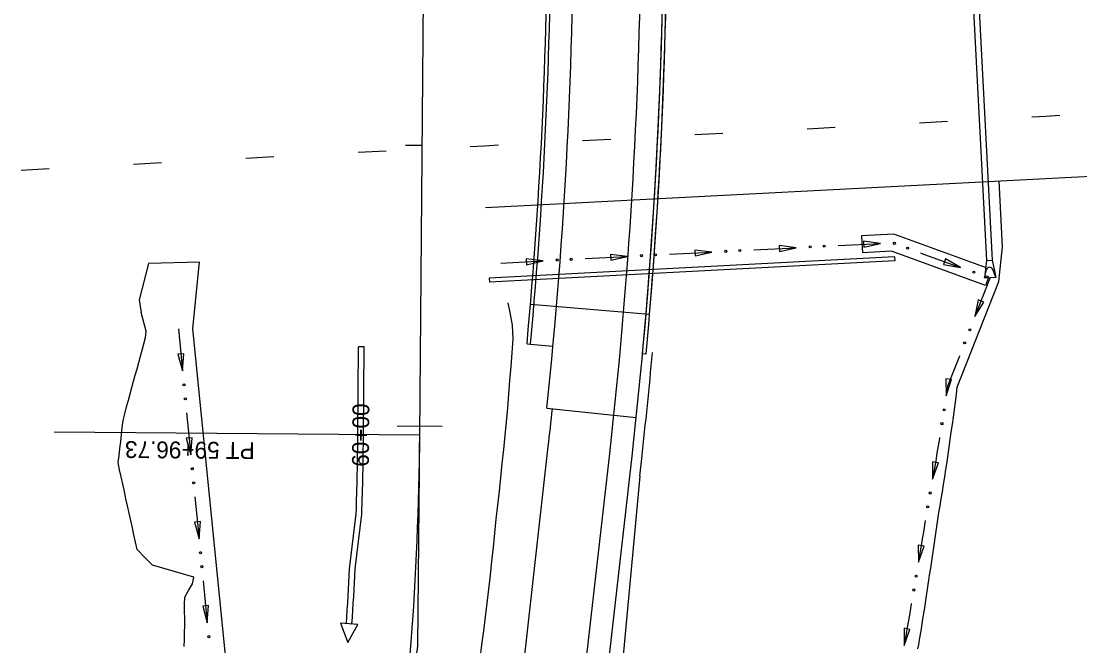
# Model space of a CAD drawing. Extents: x 1304554 to 1314558, y 2088110 to 2090513.
# Drawn here: x 1313855.1 to 1314231.7, y 2089040.4 to 2089262.8 of the extents above; entities that cross this region are included whole.
import ezdxf

# ---------------------------------------------------------------- set-up
doc = ezdxf.new("R2010")
doc.units = 0
for name, color, linetype in [('B-Sub-Retaining Wall', 7, 'Continuous'), ('MOT_Barrier Wall Stage 3', 7, 'Continuous'), ('MOT_TIAB_Stage 3', 7, 'Continuous'), ('R_Bridge', 7, 'Continuous'), ('R_Conc Ditch Paving', 7, 'Continuous'), ('R_Drainage', 7, 'Continuous'), ('R_Horz Alg', 7, 'Continuous'), ('R_Horz Alg Annot', 7, 'Continuous'), ('R_Horz Alg Stationing', 7, 'Continuous'), ('R_Proposed Const Limits', 7, 'Continuous'), ('R_Proposed Road', 7, 'Continuous'), ('R_Shld_GR', 7, 'Continuous'), ('R_Shoulder', 7, 'Continuous'), ('R_Special Ditch', 7, 'Continuous'), ('S_Striping', 7, 'Continuous')]:
    doc.layers.add(name, color=color, linetype=linetype)

msp = doc.modelspace()

# ---------------------------------------------------------------- linework, layer by layer
at = {"layer": 'B-Sub-Retaining Wall'}
for p, q in [((1314165.86, 2089178.92), (1314021.63, 2089171.31)), ((1314165.86, 2089178.92), (1314165.94, 2089177.42)), ((1314165.86, 2089178.92), (1314165.94, 2089177.42)), ((1314165.86, 2089178.92), (1314165.94, 2089177.42)), ((1314165.94, 2089177.42), (1314021.71, 2089169.82)), ((1314021.63, 2089171.31), (1314021.71, 2089169.82))]:
    msp.add_line(p, q, dxfattribs=at)
at = {"layer": 'MOT_Barrier Wall Stage 3'}
for p, q in [((1313974.91, 2089115.57), (1313975.18, 2089146.84)), ((1313977.18, 2089146.82), (1313975.18, 2089146.84)), ((1313976.91, 2089115.55), (1313977.18, 2089146.82)), ((1313971.97, 2089067.87), (1313974.31, 2089087.39)), ((1313973.97, 2089067.77), (1313976.31, 2089087.33)), ((1313972.8, 2089048.18), (1313970.8, 2089048.32))]:
    msp.add_line(p, q, dxfattribs=at)
for radius, start, end in [(1123.92, 358.06349, 359.5), (1125.92, 358.06349, 359.5), (1122.42, 356.06349, 357.06349), (1124.42, 356.06349, 357.06349)]:
    msp.add_arc((1312851.03, 2089125.37), radius, start, end, dxfattribs=at)
at = {"layer": 'MOT_TIAB_Stage 3'}
msp.add_lwpolyline([(1313971.34, 2089041.59), (1313974.93, 2089048.04), (1313968.67, 2089048.47)], close=True, dxfattribs=at)
at = {"layer": 'R_Bridge'}
for p, q in [((1314078.66, 2089158.36), (1314036.31, 2089161.9)), ((1314035.08, 2089147.95), (1314036.32, 2089147.85)), ((1314076.19, 2089144.52), (1314077.43, 2089144.42))]:
    msp.add_line(p, q, dxfattribs=at)
for radius, start, end in [(1782.95, 354.7437, 5.46314), (1784.2, 354.74404, 5.4628), (1741.7, 354.73222, 5.47462), (1742.95, 354.73258, 5.47426), (1782.95, 355.19361, 5.01323), (1784.2, 355.19363, 5.01321)]:
    msp.add_arc((1312300.74, 2089307.86), radius, start, end, dxfattribs=at)
at = {"layer": 'R_Conc Ditch Paving'}
for p, q in [((1314154.11, 2089186.35), (1314154.43, 2089180.35)), ((1314199.19, 2089171.54), (1314198.16, 2089168.72))]:
    msp.add_line(p, q, dxfattribs=at)
for points in [[(1314198.22, 2089175.08), (1314165.59, 2089186.94), (1314154.11, 2089186.35)], [(1314198.16, 2089168.72), (1314164.68, 2089180.89), (1314154.43, 2089180.35)]]:
    msp.add_lwpolyline(points, dxfattribs=at)
at = {"layer": 'R_Drainage'}
for p, q in [((1314193.48, 2089274.5), (1314198.5, 2089177.63)), ((1314195.48, 2089274.6), (1314200.5, 2089177.73)), ((1314198.5, 2089177.63), (1314197.82, 2089171.47)), ((1314198.5, 2089177.63), (1314200.5, 2089177.73)), ((1314200.5, 2089177.73), (1314201.82, 2089171.67)), ((1314197.82, 2089171.47), (1314198.57, 2089174.31)), ((1314197.82, 2089171.47), (1314201.82, 2089171.67)), ((1314201.82, 2089171.67), (1314200.78, 2089174.42)), ((1313912.99, 2089144.4), (1313910.88, 2089144.2)), ((1313912.52, 2089138.33), (1313912.99, 2089144.4)), ((1313910.88, 2089144.2), (1313912.52, 2089138.33)), ((1313915.93, 2089114.51), (1313913.82, 2089114.3)), ((1313913.82, 2089114.3), (1313915.46, 2089108.43)), ((1313915.46, 2089108.43), (1313915.93, 2089114.51)), ((1313918.87, 2089084.62), (1313916.76, 2089084.41)), ((1313916.76, 2089084.41), (1313918.4, 2089078.54)), ((1313918.4, 2089078.54), (1313918.87, 2089084.62)), ((1313921.81, 2089054.72), (1313919.7, 2089054.51)), ((1313919.7, 2089054.51), (1313921.34, 2089048.65)), ((1313921.34, 2089048.65), (1313921.81, 2089054.72))]:
    msp.add_line(p, q, dxfattribs=at)
for points in [[(1313911.06, 2089153.26), (1313912.52, 2089138.33)], [(1313913.99, 2089123.4), (1313913.99, 2089123.36)], [(1313913.99, 2089123.36), (1313915.46, 2089108.43)], [(1313916.93, 2089093.51), (1313916.93, 2089093.47)], [(1313916.93, 2089093.47), (1313918.4, 2089078.54)], [(1313919.87, 2089063.61), (1313919.88, 2089063.58)], [(1313919.88, 2089063.57), (1313921.34, 2089048.65)]]:
    msp.add_lwpolyline(points, dxfattribs=at)
for centre in [(1313913.05, 2089133.35), (1313913.54, 2089128.36), (1313915.99, 2089103.46), (1313916.48, 2089098.47), (1313918.93, 2089073.56), (1313919.42, 2089068.58), (1313921.87, 2089043.67)]:
    msp.add_circle(centre, 0.375, dxfattribs=at)
msp.add_arc((1314199.69, 2089174.02), 1.17, 20.4966, 165.4367, dxfattribs=at)
at = {"layer": 'R_Horz Alg'}
msp.add_line((1313996.9, 2089115.37), (1314000.02, 2089472.84), dxfattribs=at)
msp.add_line((1313996.9, 2089115.37), (1314000.02, 2089472.84), dxfattribs=at)
msp.add_arc((1312851.03, 2089125.37), 1145.92, 352, 359.5, dxfattribs=at)
msp.add_arc((1312851.03, 2089125.37), 1145.92, 352, 359.5, dxfattribs=at)
at = {"layer": 'R_Horz Alg Annot'}
for points in [[(1313996.9, 2089115.37), (1313866.91, 2089116.51)], [(1313985.8, 2088965.89), (1313996.25, 2089040.27), (1313996.9, 2089115.37)]]:
    msp.add_lwpolyline(points, dxfattribs=at)
at = {"layer": 'R_Horz Alg Stationing'}
for points in [[(1313991.81, 2089218.69), (1313997.81, 2089218.64)], [(1313988.93, 2089118.71), (1314004.93, 2089118.57)]]:
    msp.add_lwpolyline(points, dxfattribs=at)
at = {"layer": 'R_Proposed Const Limits'}
for points in [[(1314174.12, 2089039.32), (1314174.42, 2089040.86), (1314174.87, 2089043.32), (1314175.26, 2089045.79), (1314175.65, 2089048.27), (1314176.04, 2089050.74), (1314176.42, 2089053.21), (1314176.8, 2089055.68), (1314177.18, 2089058.16), (1314177.56, 2089060.63), (1314177.94, 2089063.1), (1314178.03, 2089063.69), (1314178.31, 2089065.58), (1314178.69, 2089068.05), (1314179.06, 2089070.52), (1314179.43, 2089073), (1314179.8, 2089075.47), (1314180.16, 2089077.95), (1314180.53, 2089080.42), (1314180.89, 2089082.9), (1314181.26, 2089085.37), (1314181.63, 2089087.84), (1314182.04, 2089090.31), (1314182.46, 2089092.78), (1314182.89, 2089095.25), (1314183.29, 2089097.89), (1314183.7, 2089100.55), (1314184.09, 2089103.21), (1314184.49, 2089105.87), (1314184.87, 2089108.53), (1314185.26, 2089111.19), (1314185.64, 2089113.85), (1314186.01, 2089116.51), (1314186.38, 2089119.18), (1314186.74, 2089121.84), (1314187.1, 2089124.51), (1314187.46, 2089127.17), (1314187.81, 2089129.84), (1314188.15, 2089132.51), (1314202.91, 2089170.09), (1314204.27, 2089182.4), (1314203.05, 2089205.9)], [(1313916.24, 2089153.35), (1313918.62, 2089176.96), (1313900.37, 2089176.49), (1313897.09, 2089163.58), (1313897.83, 2089159.07)], [(1314018.38, 2089035.82), (1314019.01, 2089040.78), (1314019.66, 2089045.74), (1314020.32, 2089050.7), (1314020.95, 2089055.66), (1314021.49, 2089060.63), (1314022.03, 2089065.6), (1314022.57, 2089070.57), (1314023.12, 2089075.54), (1314023.62, 2089080.51), (1314024.15, 2089085.49), (1314024.69, 2089090.46), (1314025.23, 2089095.43), (1314025.73, 2089100.4), (1314026.25, 2089105.38), (1314026.79, 2089110.35), (1314027.33, 2089115.28), (1314027.81, 2089120.19), (1314028.21, 2089125.1), (1314028.59, 2089130.01), (1314028.98, 2089134.93), (1314029.38, 2089139.84), (1314029.75, 2089144.75), (1314030.11, 2089149.66), (1314029.94, 2089154.62), (1314029.01, 2089159.64), (1314028.32, 2089162.56)], [(1313913.14, 2089040.15), (1313913.18, 2089042.66), (1313913.23, 2089045.17), (1313913.32, 2089047.67), (1313913.35, 2089050.19), (1313913.29, 2089052.71), (1313913.23, 2089055.23), (1313913.32, 2089057.74), (1313914.62, 2089060.11), (1313916.07, 2089062.46), (1313916.56, 2089064.92), (1313901.85, 2089069.09), (1313900.83, 2089070.16), (1313899.15, 2089071.92), (1313896.44, 2089074.74), (1313895.82, 2089077.32), (1313895.25, 2089079.9), (1313894.68, 2089082.48), (1313894.12, 2089085.06), (1313893.55, 2089087.64), (1313892.99, 2089090.22), (1313892.42, 2089092.8), (1313891.85, 2089095.38), (1313891.72, 2089095.99), (1313891.29, 2089097.96), (1313890.72, 2089100.54), (1313890.16, 2089103.12), (1313889.67, 2089105.69), (1313889.96, 2089108.17), (1313890.25, 2089110.66), (1313890.53, 2089113.14), (1313890.82, 2089115.62), (1313891.11, 2089118.11), (1313891.4, 2089120.59), (1313891.96, 2089123.04), (1313892.63, 2089125.48), (1313893.29, 2089127.93), (1313893.91, 2089130.17), (1313894.51, 2089132.39), (1313895.12, 2089134.61), (1313895.73, 2089136.83), (1313896.34, 2089139.05), (1313896.94, 2089141.28), (1313897.55, 2089143.5), (1313898.16, 2089145.73), (1313898.77, 2089147.96), (1313899.38, 2089150.18), (1313899.63, 2089152.45), (1313897.83, 2089159.07)], [(1313914.54, 2088809.73), (1313912.39, 2088821.75), (1313931.7, 2088908.87), (1313933.34, 2088937.28), (1313931.57, 2088998.96), (1313916.24, 2089153.35)]]:
    msp.add_lwpolyline(points, dxfattribs=at)
at = {"layer": 'R_Proposed Road'}
for p, q in [((1314036.32, 2089147.85), (1314044.29, 2089147.11)), ((1314042.12, 2089125.05), (1314073.94, 2089121.71)), ((1313991.22, 2088655.7), (1314042.63, 2089111.32)), ((1314013.09, 2088653.23), (1314064.49, 2089108.85))]:
    msp.add_line(p, q, dxfattribs=at)
for radius, start, end in [(1750.95, 354.00707, 6.20458), (1774.95, 353.5625, 5.5), (1774.95, 353.5625, 5.5), (1752.95, 353.5625, 354.00707)]:
    msp.add_arc((1312300.74, 2089307.86), radius, start, end, dxfattribs=at)
at = {"layer": 'R_Shld_GR'}
for p, q in [((1314075.16, 2089100.8), (1314075.87, 2089107.15)), ((1314075.17, 2089100.87), (1314059.02, 2088926.55))]:
    msp.add_line(p, q, dxfattribs=at)
msp.add_arc((1312300.69, 2089307.45), 1786.45, 353.5625, 354.77698, dxfattribs=at)
at = {"layer": 'R_Shoulder'}
for p, q in [((1314020.3, 2089196.43), (1314557.57, 2089224.28)), ((1314021.03, 2088652.34), (1314072.44, 2089107.95))]:
    msp.add_line(p, q, dxfattribs=at)
msp.add_arc((1312300.74, 2089307.86), 1782.95, 353.5625, 5.5, dxfattribs=at)
at = {"layer": 'R_Special Ditch'}
for p, q in [((1314130.8, 2089182.13), (1314124.75, 2089182.88)), ((1314124.75, 2089182.88), (1314124.86, 2089180.77)), ((1314130.8, 2089182.13), (1314124.75, 2089182.88)), ((1314124.75, 2089182.88), (1314124.86, 2089180.77)), ((1314124.86, 2089180.77), (1314130.8, 2089182.13)), ((1314124.86, 2089180.77), (1314130.8, 2089182.13)), ((1314160.79, 2089183.69), (1314154.75, 2089184.43)), ((1314154.75, 2089184.43), (1314154.86, 2089182.32)), ((1314160.79, 2089183.69), (1314154.75, 2089184.43)), ((1314154.75, 2089184.43), (1314154.86, 2089182.32)), ((1314154.86, 2089182.32), (1314160.79, 2089183.69)), ((1314154.86, 2089182.32), (1314160.79, 2089183.69)), ((1314070.8, 2089179.02), (1314064.75, 2089179.77)), ((1314064.75, 2089179.77), (1314064.86, 2089177.66)), ((1314070.8, 2089179.02), (1314064.75, 2089179.77)), ((1314064.75, 2089179.77), (1314064.86, 2089177.66)), ((1314064.86, 2089177.66), (1314070.8, 2089179.02)), ((1314064.86, 2089177.66), (1314070.8, 2089179.02)), ((1314100.8, 2089180.58), (1314094.75, 2089181.32)), ((1314094.75, 2089181.32), (1314094.86, 2089179.21)), ((1314100.8, 2089180.58), (1314094.75, 2089181.32)), ((1314094.75, 2089181.32), (1314094.86, 2089179.21)), ((1314094.86, 2089179.21), (1314100.8, 2089180.58)), ((1314094.86, 2089179.21), (1314100.8, 2089180.58)), ((1314040.8, 2089177.47), (1314034.76, 2089178.22)), ((1314034.76, 2089178.22), (1314034.86, 2089176.1)), ((1314040.8, 2089177.47), (1314034.76, 2089178.22)), ((1314034.76, 2089178.22), (1314034.86, 2089176.1)), ((1314034.86, 2089176.1), (1314040.8, 2089177.47)), ((1314034.86, 2089176.1), (1314040.8, 2089177.47)), ((1314184, 2089178.18), (1314183.28, 2089176.19)), ((1314184, 2089178.18), (1314183.28, 2089176.19)), ((1314183.28, 2089176.19), (1314189.28, 2089175.14)), ((1314183.28, 2089176.19), (1314189.28, 2089175.14)), ((1314189.28, 2089175.14), (1314184, 2089178.18)), ((1314189.28, 2089175.14), (1314184, 2089178.18)), ((1314195.56, 2089163.57), (1314194.37, 2089157.6)), ((1314195.56, 2089163.57), (1314194.37, 2089157.6)), ((1314197.53, 2089162.8), (1314195.56, 2089163.57)), ((1314197.53, 2089162.8), (1314195.56, 2089163.57)), ((1314194.37, 2089157.6), (1314197.53, 2089162.8)), ((1314194.37, 2089157.6), (1314197.53, 2089162.8)), ((1314186.12, 2089135.19), (1314184.03, 2089135.51)), ((1314184.03, 2089135.51), (1314184.19, 2089129.42)), ((1314186.12, 2089135.19), (1314184.03, 2089135.51)), ((1314184.03, 2089135.51), (1314184.19, 2089129.42)), ((1314184.19, 2089129.42), (1314186.12, 2089135.19)), ((1314184.19, 2089129.42), (1314186.12, 2089135.19)), ((1314181.41, 2089105.51), (1314179.32, 2089105.87)), ((1314179.32, 2089105.87), (1314179.34, 2089099.77)), ((1314181.41, 2089105.51), (1314179.32, 2089105.87)), ((1314179.32, 2089105.87), (1314179.34, 2089099.77)), ((1314179.34, 2089099.77), (1314181.41, 2089105.51)), ((1314179.34, 2089099.77), (1314181.41, 2089105.51)), ((1314176.33, 2089075.91), (1314174.24, 2089076.26)), ((1314174.24, 2089076.26), (1314174.3, 2089070.16)), ((1314176.33, 2089075.91), (1314174.24, 2089076.26)), ((1314174.24, 2089076.26), (1314174.3, 2089070.16)), ((1314174.3, 2089070.16), (1314176.33, 2089075.91)), ((1314174.3, 2089070.16), (1314176.33, 2089075.91)), ((1314171.31, 2089046.28), (1314169.22, 2089046.65)), ((1314169.22, 2089046.65), (1314169.23, 2089040.56)), ((1314171.31, 2089046.28), (1314169.22, 2089046.65)), ((1314169.22, 2089046.65), (1314169.23, 2089040.56)), ((1314169.23, 2089040.56), (1314171.31, 2089046.28)), ((1314169.23, 2089040.56), (1314171.31, 2089046.28))]:
    msp.add_line(p, q, dxfattribs=at)
for points in [[(1314115.82, 2089181.36), (1314130.8, 2089182.13)], [(1314115.82, 2089181.36), (1314130.8, 2089182.13)], [(1314145.78, 2089182.91), (1314145.81, 2089182.91)], [(1314145.78, 2089182.91), (1314145.81, 2089182.91)], [(1314145.81, 2089182.91), (1314160.79, 2089183.69)], [(1314145.81, 2089182.91), (1314160.79, 2089183.69)], [(1314055.82, 2089178.25), (1314070.8, 2089179.02)], [(1314055.82, 2089178.25), (1314070.8, 2089179.02)], [(1314085.78, 2089179.8), (1314085.82, 2089179.8)], [(1314085.78, 2089179.8), (1314085.82, 2089179.8)], [(1314085.82, 2089179.8), (1314100.8, 2089180.58)], [(1314085.82, 2089179.8), (1314100.8, 2089180.58)], [(1314115.78, 2089181.35), (1314115.81, 2089181.36)], [(1314115.78, 2089181.35), (1314115.81, 2089181.36)], [(1314175.15, 2089180.27), (1314175.18, 2089180.26)], [(1314175.15, 2089180.27), (1314175.18, 2089180.26)], [(1314175.18, 2089180.26), (1314189.28, 2089175.14)], [(1314175.18, 2089180.26), (1314189.28, 2089175.14)], [(1314025.82, 2089176.69), (1314040.8, 2089177.47)], [(1314025.82, 2089176.69), (1314040.8, 2089177.47)], [(1314055.78, 2089178.25), (1314055.82, 2089178.25)], [(1314055.78, 2089178.25), (1314055.82, 2089178.25)], [(1314199.82, 2089171.57), (1314194.37, 2089157.6)], [(1314199.82, 2089171.57), (1314194.37, 2089157.6)], [(1314188.9, 2089143.59), (1314184.7, 2089132.83), (1314184.3, 2089130.17), (1314184.19, 2089129.42)], [(1314188.9, 2089143.59), (1314184.7, 2089132.83), (1314184.3, 2089130.17), (1314184.19, 2089129.42)], [(1314188.91, 2089143.62), (1314188.9, 2089143.59)], [(1314188.91, 2089143.62), (1314188.9, 2089143.59)], [(1314181.84, 2089114.56), (1314181.79, 2089114.25), (1314181.35, 2089111.6), (1314180.91, 2089108.95), (1314180.46, 2089106.3), (1314180.01, 2089103.65), (1314179.55, 2089101), (1314179.34, 2089099.77)], [(1314181.84, 2089114.56), (1314181.79, 2089114.25), (1314181.35, 2089111.6), (1314180.91, 2089108.95), (1314180.46, 2089106.3), (1314180.01, 2089103.65), (1314179.55, 2089101), (1314179.34, 2089099.77)], [(1314181.85, 2089114.6), (1314181.84, 2089114.56)], [(1314181.85, 2089114.6), (1314181.84, 2089114.56)], [(1314176.74, 2089084.96), (1314176.48, 2089083.39), (1314176.08, 2089080.92), (1314175.67, 2089078.45), (1314175.27, 2089075.98), (1314174.86, 2089073.51), (1314174.45, 2089071.04), (1314174.3, 2089070.16)], [(1314176.74, 2089084.96), (1314176.48, 2089083.39), (1314176.08, 2089080.92), (1314175.67, 2089078.45), (1314175.27, 2089075.98), (1314174.86, 2089073.51), (1314174.45, 2089071.04), (1314174.3, 2089070.16)], [(1314176.74, 2089085), (1314176.74, 2089084.96)], [(1314176.74, 2089085), (1314176.74, 2089084.96)], [(1314171.79, 2089055.34), (1314171.52, 2089053.76), (1314171.1, 2089051.29), (1314170.67, 2089048.83), (1314170.24, 2089046.36), (1314169.81, 2089043.89), (1314169.38, 2089041.43), (1314169.23, 2089040.56)], [(1314171.79, 2089055.34), (1314171.52, 2089053.76), (1314171.1, 2089051.29), (1314170.67, 2089048.83), (1314170.24, 2089046.36), (1314169.81, 2089043.89), (1314169.38, 2089041.43), (1314169.23, 2089040.56)], [(1314171.8, 2089055.37), (1314171.79, 2089055.34)], [(1314171.8, 2089055.37), (1314171.79, 2089055.34)]]:
    msp.add_lwpolyline(points, dxfattribs=at)
for centre in [(1314135.79, 2089182.43), (1314135.79, 2089182.43), (1314140.8, 2089182.69), (1314140.8, 2089182.69), (1314165.77, 2089183.72), (1314165.77, 2089183.72), (1314170.47, 2089182.01), (1314170.47, 2089182.01), (1314050.8, 2089178.02), (1314050.8, 2089178.02), (1314075.8, 2089179.32), (1314075.8, 2089179.32), (1314080.8, 2089179.58), (1314080.8, 2089179.58), (1314105.79, 2089180.87), (1314105.79, 2089180.87), (1314110.8, 2089181.13), (1314110.8, 2089181.13), (1314045.8, 2089177.76), (1314045.8, 2089177.76), (1314194, 2089173.46), (1314194, 2089173.46), (1314198.71, 2089171.75), (1314198.71, 2089171.75), (1314192.58, 2089152.92), (1314192.58, 2089152.92), (1314190.76, 2089148.25), (1314190.76, 2089148.25), (1314183.46, 2089124.46), (1314183.46, 2089124.46), (1314182.68, 2089119.52), (1314182.68, 2089119.52), (1314178.49, 2089094.84), (1314178.49, 2089094.84), (1314177.6, 2089089.91), (1314177.6, 2089089.91), (1314173.51, 2089065.22), (1314173.51, 2089065.22), (1314172.67, 2089060.28), (1314172.67, 2089060.28)]:
    msp.add_circle(centre, 0.375, dxfattribs=at)
at = {"layer": 'S_Striping'}
for p, q in [((1314174.68, 2089226.63), (1314184.67, 2089227.16)), ((1314054.85, 2089220.29), (1314064.84, 2089220.82)), ((1314094.8, 2089222.42), (1314104.78, 2089222.94)), ((1313974.96, 2089216.13), (1313984.95, 2089216.65)), ((1313895.07, 2089211.89), (1313905.06, 2089212.42)), ((1313855.13, 2089209.77), (1313865.11, 2089210.3))]:
    msp.add_line(p, q, dxfattribs=at)
for points in [[(1314214.63, 2089228.75), (1314219.62, 2089229.01), (1314224.61, 2089229.28)], [(1314134.74, 2089224.52), (1314144.72, 2089225.05), (1314144.73, 2089225.05)], [(1314014.91, 2089218.21), (1314019.9, 2089218.47), (1314024.89, 2089218.73)], [(1313935.02, 2089214.02), (1313945, 2089214.56), (1313945, 2089214.56)]]:
    msp.add_lwpolyline(points, dxfattribs=at)

# ---------------------------------------------------------------- texts
at = {"layer": 'R_Horz Alg Annot'}
msp.add_text('PT 59+96.73', height=6, rotation=179.5, dxfattribs=at).set_placement((1313938.25, 2089112.89))
at = {"layer": 'R_Horz Alg Stationing'}
msp.add_text('60+00', height=6, rotation=89.5, dxfattribs=at).set_placement((1313978.81, 2089104.16))

doc.saveas('drawing.dxf')
